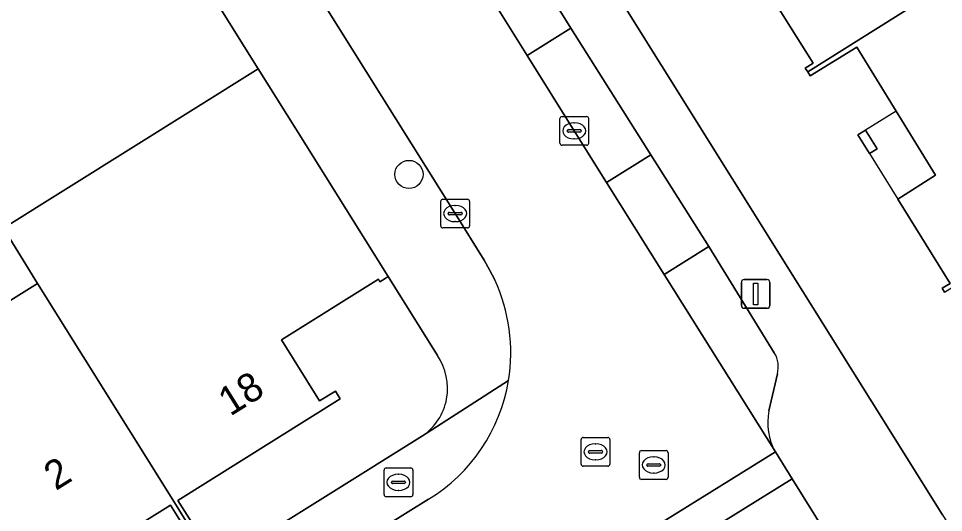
# Model space of a CAD drawing. Extents: x 158835 to 160077, y 386387 to 387778.
# Drawn here: x 159126.05 to 159158.2, y 387103.8 to 387120.98 of the extents above; entities that cross this region are included whole.
import ezdxf

# ---------------------------------------------------------------- set-up
doc = ezdxf.new("R2010")
doc.units = 0
for name, color, linetype in [('IMGEO_Boom', 7, 'Continuous'), ('IMGEO_Brandkraan', 7, 'Continuous'), ('IMGEO_Erf', 7, 'Continuous'), ('IMGEO_Kolk', 7, 'Continuous'), ('IMGEO_Lichtmast', 7, 'Continuous'), ('IMGEO_Muur', 7, 'Continuous'), ('IMGEO_Pand', 7, 'Continuous'), ('IMGEO_Pand_nummerreeks', 7, 'Continuous'), ('IMGEO_Pand_overbouw', 7, 'Continuous'), ('IMGEO_Parkeervlak_open', 7, 'Continuous'), ('IMGEO_Rijbaan_lokaal_open', 7, 'Continuous'), ('IMGEO_Rioolput', 7, 'Continuous'), ('IMGEO_Voetpad_open', 7, 'Continuous')]:
    doc.layers.add(name, color=color, linetype=linetype)

msp = doc.modelspace()

# ---------------------------------------------------------------- linework, layer by layer
at = {"layer": 'IMGEO_Boom'}
msp.add_circle((159139.621, 387115.556), 0.489, dxfattribs=at)
at = {"layer": 'IMGEO_Brandkraan'}
for p, q in [((159138.83, 387105.352), (159139.682, 387105.352)), ((159138.755, 387104.426), (159138.755, 387105.278)), ((159139.243, 387105.132), (159139.268, 387105.132)), ((159139.756, 387105.278), (159139.756, 387104.426)), ((159139.014, 387104.846), (159139.014, 387104.858)), ((159139.452, 387104.809), (159139.054, 387104.809)), ((159139.057, 387104.895), (159139.455, 387104.895)), ((159139.498, 387104.858), (159139.498, 387104.846)), ((159139.266, 387104.572), (159139.241, 387104.572)), ((159139.682, 387104.352), (159138.83, 387104.352))]:
    msp.add_line(p, q, dxfattribs=at)
for points in [[(159138.83, 387105.352), (159139.682, 387105.352)], [(159138.755, 387104.426), (159138.755, 387105.278)], [(159139.756, 387105.278), (159139.756, 387104.426)], [(159139.682, 387104.352), (159138.83, 387104.352)]]:
    msp.add_lwpolyline(points, dxfattribs=at)
for centre, radius, start, end in [((159138.832, 387105.276), 0.0765, 91.552, 178.448), ((159138.832, 387105.276), 0.0765, 91.552, 178.448), ((159139.68, 387105.276), 0.0765, 1.552, 88.448), ((159139.68, 387105.276), 0.0765, 1.552, 88.448), ((159139.054, 387104.855), 0.0403, 85.8775, 175.7526), ((159139.051, 387104.845), 0.0366, 178.938, 274.7102), ((159139.455, 387104.852), 0.043, 264.8664, 352.4533), ((159139.459, 387104.857), 0.0386, 1.7309, 96.639), ((159138.832, 387104.428), 0.0765, 181.552, 268.448), ((159138.832, 387104.428), 0.0765, 181.552, 268.448), ((159139.68, 387104.428), 0.0765, 271.552, 358.448), ((159139.68, 387104.428), 0.0765, 271.552, 358.448)]:
    msp.add_arc(centre, radius, start, end, dxfattribs=at)
for centre, major_axis, ratio, start_param, end_param in [((159139.242, 387104.852), (-0.387, 0.002), 0.722429, 4.712389, 7.853982), ((159139.267, 387104.852), (-0.39, 0.002), 0.717154, 1.570796, 4.712389)]:
    msp.add_ellipse(centre, major_axis=major_axis, ratio=ratio, start_param=start_param, end_param=end_param, dxfattribs=at)
at = {"layer": 'IMGEO_Erf'}
for points in [[(159131.202, 387146.887), (159138.432, 387135.312), (159143.549, 387127.119), (159158.165, 387103.724), (159222.278, 387001.075)], [(159158.243, 387111.464), (159158.159, 387111.6), (159158.43, 387111.769), (159156.612, 387114.7), (159157.927, 387115.535), (159156.561, 387117.756), (159155.192, 387119.981), (159153.566, 387118.981), (159153.482, 387119.116), (159153.397, 387119.252), (159153.668, 387119.421), (159151.845, 387122.343), (159153.213, 387123.198), (159151.753, 387125.399), (159150.316, 387127.566), (159150.141, 387127.846), (159149.734, 387127.591), (159148.139, 387130.142), (159152.378, 387132.794), (159153.648, 387133.588), (159155.243, 387131.037), (159161.024, 387134.652)], [(159111.423, 387102.222), (159116.529, 387105.412), (159121.584, 387108.569), (159126.706, 387111.769), (159125.529, 387113.683), (159134.38, 387119.23), (159128.914, 387127.985), (159128.897, 387128.013), (159123.365, 387124.544), (159124.428, 387122.85), (159121.089, 387120.756), (159117.647, 387118.597), (159116.585, 387120.292), (159113.215, 387118.179), (159114.278, 387116.484), (159110.924, 387114.381), (159107.497, 387112.232), (159106.435, 387113.926), (159104.767, 387112.88), (159100.938, 387119.036)], [(159140.608, 387109.256), (159138.894, 387112.002), (159138.79, 387111.938), (159138.611, 387111.826), (159138.558, 387111.911), (159135.194, 387109.803), (159136.514, 387107.682), (159137.065, 387108.025), (159137.234, 387107.754), (159131.587, 387104.225), (159132.23, 387103.196)], [(159092.005, 387076.397), (159140.091, 387106.463)], [(159131.967, 387103.036), (159131.326, 387104.062), (159126.487, 387101.039)]]:
    msp.add_lwpolyline(points, dxfattribs=at)
msp.add_lwpolyline([(159155.632, 387116.281), (159155.226, 387116.935), (159155.49, 387117.097), (159155.895, 387116.444)], close=True, dxfattribs=at)
msp.add_arc((159138.96, 387108.117), 2.003, 304.3688, 34.6571, dxfattribs=at)
at = {"layer": 'IMGEO_Kolk'}
for p, q in [((159144.942, 387117.569), (159145.794, 387117.569)), ((159144.867, 387116.643), (159144.867, 387117.495)), ((159145.355, 387117.349), (159145.38, 387117.349)), ((159145.868, 387117.495), (159145.868, 387116.643)), ((159145.126, 387117.063), (159145.126, 387117.075)), ((159145.564, 387117.026), (159145.166, 387117.026)), ((159145.169, 387117.112), (159145.567, 387117.112)), ((159145.61, 387117.075), (159145.61, 387117.063)), ((159145.378, 387116.789), (159145.353, 387116.789)), ((159145.794, 387116.569), (159144.942, 387116.569)), ((159140.802, 387114.694), (159141.654, 387114.694)), ((159140.727, 387113.768), (159140.727, 387114.62)), ((159141.215, 387114.474), (159141.24, 387114.474)), ((159141.728, 387114.62), (159141.728, 387113.768)), ((159140.986, 387114.188), (159140.986, 387114.2)), ((159141.424, 387114.151), (159141.026, 387114.151)), ((159141.029, 387114.237), (159141.427, 387114.237)), ((159141.47, 387114.2), (159141.47, 387114.188)), ((159141.654, 387113.694), (159140.802, 387113.694)), ((159141.238, 387113.914), (159141.213, 387113.914))]:
    msp.add_line(p, q, dxfattribs=at)
for points in [[(159144.942, 387117.569), (159145.794, 387117.569)], [(159144.867, 387116.643), (159144.867, 387117.495)], [(159145.868, 387117.495), (159145.868, 387116.643)], [(159145.794, 387116.569), (159144.942, 387116.569)], [(159140.802, 387114.694), (159141.654, 387114.694)], [(159140.727, 387113.768), (159140.727, 387114.62)], [(159141.728, 387114.62), (159141.728, 387113.768)], [(159141.654, 387113.694), (159140.802, 387113.694)]]:
    msp.add_lwpolyline(points, dxfattribs=at)
for centre, radius, start, end in [((159144.944, 387117.493), 0.0765, 91.552, 178.448), ((159144.944, 387117.493), 0.0765, 91.552, 178.448), ((159145.792, 387117.493), 0.0765, 1.552, 88.448), ((159145.792, 387117.493), 0.0765, 1.552, 88.448), ((159145.166, 387117.072), 0.0403, 85.8775, 175.7526), ((159145.163, 387117.062), 0.0366, 178.938, 274.7102), ((159145.567, 387117.069), 0.043, 264.8664, 352.4533), ((159145.571, 387117.074), 0.0386, 1.7309, 96.639), ((159144.944, 387116.645), 0.0765, 181.552, 268.448), ((159144.944, 387116.645), 0.0765, 181.552, 268.448), ((159145.792, 387116.645), 0.0765, 271.552, 358.448), ((159145.792, 387116.645), 0.0765, 271.552, 358.448), ((159140.804, 387114.618), 0.0765, 91.552, 178.448), ((159140.804, 387114.618), 0.0765, 91.552, 178.448), ((159141.652, 387114.618), 0.0765, 1.552, 88.448), ((159141.652, 387114.618), 0.0765, 1.552, 88.448), ((159141.026, 387114.197), 0.0403, 85.8775, 175.7526), ((159141.023, 387114.187), 0.0366, 178.938, 274.7102), ((159141.427, 387114.194), 0.043, 264.8664, 352.4533), ((159141.431, 387114.199), 0.0386, 1.7309, 96.639), ((159140.804, 387113.77), 0.0765, 181.552, 268.448), ((159140.804, 387113.77), 0.0765, 181.552, 268.448), ((159141.652, 387113.77), 0.0765, 271.552, 358.448), ((159141.652, 387113.77), 0.0765, 271.552, 358.448)]:
    msp.add_arc(centre, radius, start, end, dxfattribs=at)
for centre, major_axis, ratio, start_param, end_param in [((159145.354, 387117.069), (-0.387, 0.002), 0.722429, 4.712389, 7.853982), ((159145.379, 387117.069), (-0.39, 0.002), 0.717154, 1.570796, 4.712389), ((159141.214, 387114.194), (-0.387, 0.002), 0.722429, 4.712389, 7.853982), ((159141.239, 387114.194), (-0.39, 0.002), 0.717154, 1.570796, 4.712389)]:
    msp.add_ellipse(centre, major_axis=major_axis, ratio=ratio, start_param=start_param, end_param=end_param, dxfattribs=at)
at = {"layer": 'IMGEO_Lichtmast'}
for p, q in [((159151.177, 387111.003), (159151.177, 387111.803)), ((159151.177, 387111.803), (159151.177, 387111.003)), ((159151.277, 387111.903), (159152.067, 387111.903)), ((159152.067, 387111.903), (159151.277, 387111.903)), ((159152.167, 387111.803), (159152.167, 387111.003)), ((159152.167, 387111.003), (159152.167, 387111.803)), ((159152.067, 387110.903), (159151.277, 387110.903)), ((159151.277, 387110.903), (159152.067, 387110.903))]:
    msp.add_line(p, q, dxfattribs=at)
msp.add_lwpolyline([(159151.597, 387111.778), (159151.747, 387111.778), (159151.747, 387111.028), (159151.597, 387111.028), (159151.597, 387111.778)], dxfattribs=at)
for centre, start, end in [((159151.277, 387111.803), 90, 180), ((159151.277, 387111.803), 90, 180), ((159152.067, 387111.803), 0, 90), ((159152.067, 387111.803), 360, 90), ((159151.277, 387111.003), 180, 270), ((159151.277, 387111.003), 180, 270), ((159152.067, 387111.003), 270, 0), ((159152.067, 387111.003), 270, 0)]:
    msp.add_arc(centre, 0.1, start, end, dxfattribs=at)
at = {"layer": 'IMGEO_Muur'}
msp.add_lwpolyline([(159128.914, 387127.985), (159134.38, 387119.23), (159135.688, 387117.136)], dxfattribs=at)
at = {"layer": 'IMGEO_Pand'}
for points in [[(159161.205, 387128.669), (159163.485, 387130.095), (159160.914, 387134.206), (159161.194, 387134.38), (159161.024, 387134.652), (159155.243, 387131.037), (159150.141, 387127.846), (159150.316, 387127.566), (159151.753, 387125.399), (159153.213, 387123.198), (159151.845, 387122.343), (159153.668, 387119.421), (159153.397, 387119.252), (159153.482, 387119.116), (159163.315, 387125.296)], [(159163.315, 387125.296), (159153.482, 387119.116), (159153.566, 387118.981), (159155.192, 387119.981), (159156.561, 387117.756), (159157.927, 387115.535), (159156.612, 387114.7), (159158.43, 387111.769), (159158.159, 387111.6), (159158.243, 387111.464), (159168.101, 387117.642)], [(159135.194, 387109.803), (159138.558, 387111.911), (159138.611, 387111.826), (159138.79, 387111.938), (159138.894, 387112.002), (159135.688, 387117.136), (159134.38, 387119.23), (159125.529, 387113.683), (159126.706, 387111.769), (159131.467, 387104.151), (159132.109, 387103.123), (159132.23, 387103.196), (159131.587, 387104.225), (159137.234, 387107.754), (159137.065, 387108.025), (159136.514, 387107.682)], [(159155.49, 387117.097), (159155.226, 387116.935), (159155.632, 387116.281), (159155.895, 387116.444)], [(159126.99, 387099.916), (159127.133, 387100.004), (159126.487, 387101.039), (159131.326, 387104.062), (159131.967, 387103.036), (159132.109, 387103.123), (159131.467, 387104.151), (159126.706, 387111.769), (159121.584, 387108.569), (159126.345, 387100.95)]]:
    msp.add_lwpolyline(points, close=True, dxfattribs=at)
at = {"layer": 'IMGEO_Pand_overbouw'}
msp.add_lwpolyline([(159156.612, 387114.7), (159157.927, 387115.535), (159156.561, 387117.756), (159155.49, 387117.097), (159155.226, 387116.935), (159155.632, 387116.281)], close=True, dxfattribs=at)
at = {"layer": 'IMGEO_Parkeervlak_open'}
msp.add_lwpolyline([(159145.253, 387120.644), (159143.728, 387119.694), (159145.363, 387117.069), (159146.487, 387115.275), (159148.034, 387116.241)], close=True, dxfattribs=at)
for points in [[(159150.042, 387113.049), (159148.492, 387112.077), (159152.358, 387105.91)], [(159152.323, 387109.35), (159150.042, 387113.049)], [(159152.135, 387107.339), (159152.428, 387108.624)]]:
    msp.add_lwpolyline(points, dxfattribs=at)
for centre, radius, start, end in [((159151.564, 387108.87), 0.898, 344.1352, 32.3239), ((159154.152, 387106.922), 2.06, 168.3166, 209.4227)]:
    msp.add_arc(centre, radius, start, end, dxfattribs=at)
at = {"layer": 'IMGEO_Rijbaan_lokaal_open'}
for points in [[(159186.985, 387195.824), (159182.901, 387193.183), (159182.797, 387193.116), (159182.679, 387193.04), (159174.039, 387187.668), (159173.315, 387187.218), (159173.218, 387187.157), (159168.759, 387184.361), (159149.771, 387172.508), (159129.852, 387160.089), (159124.698, 387156.88), (159121.887, 387155.13), (159117.406, 387152.34), (159119.888, 387148.372), (159130.485, 387131.344), (159141.225, 387114.195), (159142.231, 387112.577), (159142.423, 387112.239), (159142.602, 387111.89)], [(159145.475, 387101.632), (159152.358, 387105.91), (159148.492, 387112.077), (159146.487, 387115.275), (159145.363, 387117.069), (159143.728, 387119.694), (159140.143, 387125.45), (159134.862, 387133.929), (159127.465, 387145.688)], [(159140.304, 387104.262), (159137.382, 387102.443)]]:
    msp.add_lwpolyline(points, dxfattribs=at)
for centre, radius, start, end in [((159137.188, 387109.367), 5.973, 350.562, 24.9829), ((159137.178, 387109.362), 5.982, 301.5059, 350.6282)]:
    msp.add_arc(centre, radius, start, end, dxfattribs=at)
at = {"layer": 'IMGEO_Rioolput'}
for p, q in [((159145.606, 387105.486), (159145.606, 387106.338)), ((159145.681, 387106.412), (159146.533, 387106.412)), ((159146.607, 387106.338), (159146.607, 387105.486)), ((159146.094, 387106.192), (159146.119, 387106.192)), ((159145.865, 387105.906), (159145.865, 387105.918)), ((159146.303, 387105.869), (159145.905, 387105.869)), ((159145.908, 387105.955), (159146.306, 387105.955)), ((159146.349, 387105.918), (159146.349, 387105.906)), ((159147.63, 387105.029), (159147.63, 387105.881)), ((159147.705, 387105.955), (159148.557, 387105.955)), ((159148.118, 387105.735), (159148.143, 387105.735)), ((159148.631, 387105.881), (159148.631, 387105.029)), ((159146.533, 387105.412), (159145.681, 387105.412)), ((159146.117, 387105.632), (159146.092, 387105.632)), ((159147.889, 387105.449), (159147.889, 387105.461)), ((159148.327, 387105.412), (159147.929, 387105.412)), ((159147.932, 387105.498), (159148.33, 387105.498)), ((159148.373, 387105.461), (159148.373, 387105.449)), ((159148.141, 387105.175), (159148.116, 387105.175)), ((159148.557, 387104.955), (159147.705, 387104.955))]:
    msp.add_line(p, q, dxfattribs=at)
for points in [[(159145.606, 387105.486), (159145.606, 387106.338)], [(159145.681, 387106.412), (159146.533, 387106.412)], [(159146.607, 387106.338), (159146.607, 387105.486)], [(159147.63, 387105.029), (159147.63, 387105.881)], [(159147.705, 387105.955), (159148.557, 387105.955)], [(159148.631, 387105.881), (159148.631, 387105.029)], [(159146.533, 387105.412), (159145.681, 387105.412)], [(159148.557, 387104.955), (159147.705, 387104.955)]]:
    msp.add_lwpolyline(points, dxfattribs=at)
for centre, radius, start, end in [((159145.683, 387106.336), 0.0765, 91.552, 178.448), ((159145.683, 387106.336), 0.0765, 91.552, 178.448), ((159146.531, 387106.336), 0.0765, 1.552, 88.448), ((159146.531, 387106.336), 0.0765, 1.552, 88.448), ((159145.905, 387105.915), 0.0403, 85.8775, 175.7526), ((159145.902, 387105.905), 0.0366, 178.938, 274.7102), ((159146.306, 387105.912), 0.043, 264.8664, 352.4533), ((159146.31, 387105.917), 0.0386, 1.7309, 96.639), ((159147.707, 387105.879), 0.0765, 91.552, 178.448), ((159147.707, 387105.879), 0.0765, 91.552, 178.448), ((159148.555, 387105.879), 0.0765, 1.552, 88.448), ((159148.555, 387105.879), 0.0765, 1.552, 88.448), ((159145.683, 387105.488), 0.0765, 181.552, 268.448), ((159145.683, 387105.488), 0.0765, 181.552, 268.448), ((159146.531, 387105.488), 0.0765, 271.552, 358.448), ((159146.531, 387105.488), 0.0765, 271.552, 358.448), ((159147.929, 387105.458), 0.0403, 85.8775, 175.7526), ((159147.926, 387105.448), 0.0366, 178.938, 274.7102), ((159148.33, 387105.455), 0.043, 264.8664, 352.4533), ((159148.334, 387105.46), 0.0386, 1.7309, 96.639), ((159147.707, 387105.031), 0.0765, 181.552, 268.448), ((159147.707, 387105.031), 0.0765, 181.552, 268.448), ((159148.555, 387105.031), 0.0765, 271.552, 358.448), ((159148.555, 387105.031), 0.0765, 271.552, 358.448)]:
    msp.add_arc(centre, radius, start, end, dxfattribs=at)
for centre, major_axis, ratio, start_param, end_param in [((159146.093, 387105.912), (-0.387, 0.002), 0.722429, 4.712389, 7.853982), ((159146.118, 387105.912), (-0.39, 0.002), 0.717154, 1.570796, 4.712389), ((159148.117, 387105.455), (-0.387, 0.002), 0.722429, 4.712389, 7.853982), ((159148.142, 387105.455), (-0.39, 0.002), 0.717154, 1.570796, 4.712389)]:
    msp.add_ellipse(centre, major_axis=major_axis, ratio=ratio, start_param=start_param, end_param=end_param, dxfattribs=at)
at = {"layer": 'IMGEO_Voetpad_open'}
for points in [[(159096.051, 387180.526), (159098.894, 387176.097), (159098.935, 387175.998), (159128.1, 387129.289), (159128.897, 387128.013), (159128.914, 387127.985), (159134.38, 387119.23), (159135.688, 387117.136), (159138.894, 387112.002), (159140.608, 387109.256)], [(159158.165, 387103.724), (159143.549, 387127.119), (159138.432, 387135.312), (159131.202, 387146.887), (159131.196, 387146.888), (159127.653, 387152.416)], [(159142.602, 387111.89), (159142.423, 387112.239), (159142.231, 387112.577), (159141.225, 387114.195), (159130.485, 387131.344), (159119.888, 387148.372)], [(159130.521, 387144.242), (159141.666, 387126.399), (159145.253, 387120.644), (159148.034, 387116.241), (159150.042, 387113.049), (159152.323, 387109.35)], [(159152.428, 387108.624), (159152.135, 387107.339)], [(159143.08, 387108.388), (159140.091, 387106.463), (159092.005, 387076.397), (159089.207, 387074.648), (159086.674, 387073.064), (159078.525, 387067.969), (159067.868, 387061.308), (159063.036, 387058.319), (159058.826, 387055.683), (159056.14, 387053.974), (159055.192, 387053.386), (159050.577, 387050.525), (159048.428, 387049.192), (159052.552, 387042.529), (159052.677, 387042.36)], [(159140.091, 387106.463), (159143.08, 387108.388)], [(159152.358, 387105.91), (159152.939, 387104.976), (159154.966, 387101.718), (159155.081, 387101.534), (159155.167, 387101.398), (159155.342, 387101.198)], [(159141.336, 387093.187), (159150.705, 387099.04), (159154.966, 387101.718), (159152.939, 387104.976), (159145.689, 387100.47), (159145.108, 387101.404)], [(159104.81, 387082.095), (159121.021, 387092.233), (159137.382, 387102.443), (159140.304, 387104.262)]]:
    msp.add_lwpolyline(points, dxfattribs=at)
for points in [[(159141.666, 387126.399), (159140.143, 387125.45), (159143.728, 387119.694), (159145.253, 387120.644)], [(159148.034, 387116.241), (159146.487, 387115.275), (159148.492, 387112.077), (159150.042, 387113.049)], [(159152.358, 387105.91), (159145.475, 387101.632), (159145.108, 387101.404), (159145.689, 387100.47), (159152.939, 387104.976)]]:
    msp.add_lwpolyline(points, close=True, dxfattribs=at)
for centre, radius, start, end in [((159137.188, 387109.367), 5.973, 350.562, 24.9829), ((159138.96, 387108.117), 2.003, 304.3688, 34.6571), ((159151.564, 387108.87), 0.898, 344.1352, 32.3239), ((159137.178, 387109.362), 5.982, 301.5059, 350.6282), ((159154.152, 387106.922), 2.06, 168.3166, 209.4227)]:
    msp.add_arc(centre, radius, start, end, dxfattribs=at)

# ---------------------------------------------------------------- texts
at = {"layer": 'IMGEO_Pand_nummerreeks'}
for s, rotation, p in [('18', 32.0054, (159133.405, 387107.13)), ('2', 31.9996, (159127.342, 387104.546))]:
    msp.add_text(s, height=1, rotation=rotation, dxfattribs=at).set_placement(p)

doc.saveas('drawing.dxf')
